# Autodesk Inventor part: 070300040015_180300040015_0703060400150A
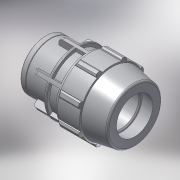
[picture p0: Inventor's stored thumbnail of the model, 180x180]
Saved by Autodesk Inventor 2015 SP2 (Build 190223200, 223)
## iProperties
Created: 2017-02
Part Number: 070300040015_180300040015_0703060400150A
Material: PVC-Piping
Description: PLASSON FEMALE ADAPTOR 40-1.1/2"
Document SubType Name: Modeling
Designer: KIM
Mass: 92.6774 g
Surface Area: 199.44 cm^2
Volume: 66.1981 cm^3
Density: 1.4 g/cm^3
Appearance: Smooth - White
Author: KIM
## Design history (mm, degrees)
derived "07030.ipt"
feature "Solid1::07030.ipt"
tag "TaggingFeature1"
body "Solid1"
other parameters: "d4" = 16.28571, "d5" = 28.5, "d7" = 82, "d9" = 16.28571, "d11" = 3.25714, "d12" = 65.6, "d13" = 120 deg, "d15" = 10 deg, "d16" = 73.8, "d18" = 2, "d19" = 35 deg, "d20" = 17.5 deg, "d21" = 76.26, "d23" = 0, "d25" = 360 deg, "d27" = 1.64, "d34" = 4.1, "d35" = 34.2, "d36" = 0, "d42" = 28.5, "d43" = 2.46, "d46" = 1.2, "d49" = 84, "d51" = 114, "d53" = 0.8, "d55" = 360 deg, "d61" = 25, "d62" = 32, "d63" = 44.845, "d64" = 38, "d65" = 4.1, "d66" = 0.5, "d67" = 1, "d68" = 7.5, "d69" = 59.04, "d70" = 2.05, "E_" = 82, "H_" = 114, "l_" = 84, "l_2" = 25, "Rp_" = 44.845
